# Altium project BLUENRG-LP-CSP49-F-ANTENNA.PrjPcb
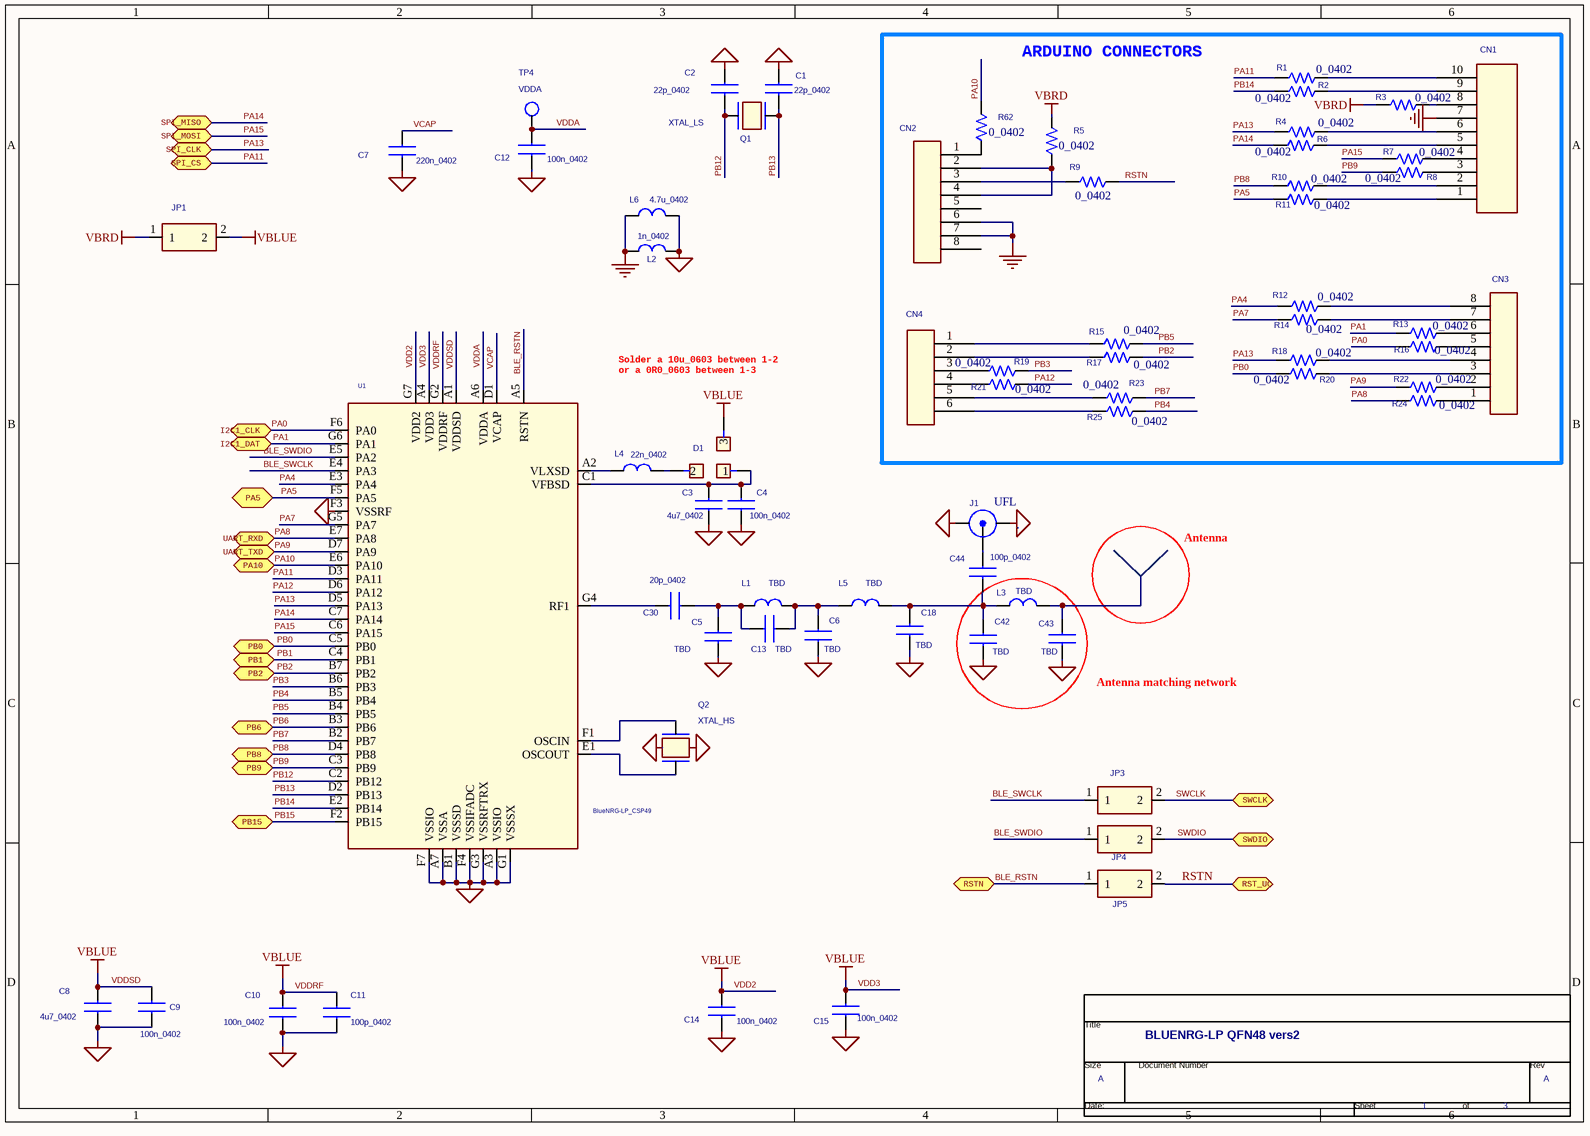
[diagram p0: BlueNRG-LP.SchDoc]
3 sheets, 160 parts. Net scope: flat (ports and power ports of the same name join across sheets).
Board file: BLUENRG-LP_CSP49_F_ANTENNA.PcbDoc
Sheets:
  BlueNRG-LP.SchDoc
  Supply.SchDoc
  USB_MICRO.SchDoc

## Sheet BlueNRG-LP.SchDoc
size 297 x 209 mm

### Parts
(Parts that share a designator on the sheet are numbered #1, #2 ... from top to bottom, then left to right.)
*#1  Page Count: 3  Page Number: 1  Page Size: A  Title: BLUENRG-LP QFN48 vers2  (hidden comment: TitleBlock0)  (graphical)
C1  22p_0402  [0402_CAP_NP]
C2  22p_0402  [0402_CAP_NP]
C3  4u7_0402  [0402_CAP_NP]
C4  100n_0402  [0402_CAP_NP]
C5  TBD  [0402_CAP_NP]
C6  TBD  [0402_CAP_NP]
C7  220n_0402  [0402_CAP_NP]
C8  4u7_0402  [0402_CAP_NP]
C9  100n_0402  [0402_CAP_NP]
C10  100n_0402  [0402_CAP_NP]
C11  100p_0402  [0402_CAP_NP]
C12  100n_0402  [0402_CAP_NP]
C13  TBD  [0402_CAP_NP]
C14  100n_0402  [0402_CAP_NP]
C15  100n_0402  [0402_CAP_NP]
C18  TBD  [0402_CAP_NP]
C30  20p_0402  [0402_CAP_NP]
C42  TBD  [0402_CAP_NP]
C43  TBD  [0402_CAP_NP]
C44  100p_0402  [0402_CAP_NP]
CN1  CON10  [HDR1X10]  (value not drawn)
CN2  CON8  [HDR1X8]  (value not drawn)
CN3  CON8  [HDR1X8]  (value not drawn)
CN4  CON6  [HDR1X6]  (value not drawn)
D1  DEV3L  [DEV3L0603_VERS1]  (value not drawn)
J1  UFL  [UFL_SMT]
JP1  JUMPER 2  [HDR 2 X 1 M]  (value not drawn)
JP3  JUMPER 2  [HDR 2 X 1 M]  (value not drawn)
JP4  JUMPER 2  [HDR 2 X 1 M]  (value not drawn)
JP5  JUMPER 2  [HDR 2 X 1 M]  (value not drawn)
L1  TBD  [0402-A]
L2  1n_0402  [0402-A]
L3  TBD  [0402-A]
L4  22n_0402  [0402-A]
L5  TBD  [0402-A]
L6  4.7u_0402  [CAP 0603]
Q1  XTAL_LS  [NX2012SA]
Q2  XTAL_HS  [NX2016SA]
R1  0_0402  [0402_RESISTOR]
R2  0_0402  [0402_RESISTOR]
R3  0_0402  [0402_RESISTOR]
R4  0_0402  [0402_RESISTOR]
R5  0_0402  [0402_RESISTOR]
R6  0_0402  [0402_RESISTOR]
R7  0_0402  [0402_RESISTOR]
R8  0_0402  [0402_RESISTOR]
R9  0_0402  [0402_RESISTOR]
R10  0_0402  [0402_RESISTOR]
R11  0_0402  [0402_RESISTOR]
R12  0_0402  [0402_RESISTOR]
R13  0_0402  [0402_RESISTOR]
R14  0_0402  [0402_RESISTOR]
R15  0_0402  [0402_RESISTOR]
R16  0_0402  [0402_RESISTOR]
R17  0_0402  [0402_RESISTOR]
R18  0_0402  [0402_RESISTOR]
R19  0_0402  [0402_RESISTOR]
R20  0_0402  [0402_RESISTOR]
R21  0_0402  [0402_RESISTOR]
R22  0_0402  [0402_RESISTOR]
R23  0_0402  [0402_RESISTOR]
R24  0_0402  [0402_RESISTOR]
R25  0_0402  [0402_RESISTOR]
R62  0_0402  [0402_RESISTOR]
TP4  VDDA  [FIDUCIAL]
U1  BlueNRG-LP_CSP49  [WLCSP49_REV1]

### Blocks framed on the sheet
ARDUINO CONNECTORS: CN1-CN4 R1-R25 R62

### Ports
I2C1_CLK (bidir), I2C1_DAT (bidir), PA5 (bidir), PA10 (bidir), PB0 (bidir), PB1 (bidir), PB2 (bidir), PB6 (bidir), PB8 (bidir), PB9 (bidir), PB15 (bidir), RST_UC (bidir), RSTN (bidir), SPI_CLK (bidir), SPI_CS (bidir), SPI_MISO (bidir), SPI_MOSI (bidir), SWCLK (bidir), SWDIO (bidir), UART_RXD (bidir), UART_TXD (bidir)

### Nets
GND: CN1.7 CN2.6 CN2.7 L2.1 L6.1
GND_RF: C1.1 C2.1 C3.1 C4.1 C5.1 C6.1 C7.1 C8.1 C9.1 C10.1 C11.1 C12.1 C14.1 C15.1 C18.1 C42.1 C43.1 J1.1 J1.3 L2.2 L6.2 Q2.2 Q2.4(gnd1) U1.A3(VSSIO) U1.A7(VSSA) U1.B1(VSSSD) U1.F3(VSSRF) U1.F4(VSSIFADC) U1.F7(VSSIO) U1.G1(VSSSX) U1.G3(VSSRFTRX)
VBRD: JP1.1 R3.1 R5.2  [project net VDD_1]
VDD2: C8.2 C9.2 C10.2 C11.2 C14.2 C15.2 D1.3 JP1.2 U1.A1(VDDSD) U1.A4(VDD3) U1.G2(VDDRF) U1.G7(VDD2)  [also labelled VBLUE, VDD3, VDDRF, VDDSD]
BLE_RSTN: JP5.1 U1.A5(RSTN) ; port RSTN
BLE_SWCLK: JP3.1 U1.E4(PA3)
BLE_SWDIO: JP4.1 U1.E5(PA2)
PA0: R16.1 U1.F6(PA0) ; port I2C1_CLK
PA1: R13.1 U1.G6(PA1) ; port I2C1_DAT
PA4: R12.1 U1.E3(PA4)
PA5: R11.1 U1.F5(PA5) ; port PA5
PA7: R14.1 U1.G5(PA7)
PA8: R24.1 U1.E7(PA8) ; port UART_RXD
PA9: R22.1 U1.D7(PA9) ; port UART_TXD
PA10: R62.2 U1.E6(PA10) ; port PA10
PA11: R1.1 U1.D3(PA11) ; port SPI_CS
PA12: R21.2 U1.D6(PA12)
PA13: R4.1 R18.1 U1.D5(PA13) ; port SPI_CLK
PA14: R6.1 U1.C7(PA14) ; port SPI_MISO
PA15: R7.1 U1.C6(PA15) ; port SPI_MOSI
PB0: R20.1 U1.C5(PB0) ; port PB0
PB1: U1.C4(PB1) ; port PB1
PB2: R17.2 U1.B7(PB2) ; port PB2
PB3: R19.2 U1.B6(PB3)
PB4: R25.2 U1.B5(PB4)
PB5: R15.2 U1.B4(PB5)
PB6: U1.B3(PB6) ; port PB6
PB7: R23.2 U1.B2(PB7)
PB8: R10.1 U1.D4(PB8) ; port PB8
PB9: R8.1 U1.C3(PB9) ; port PB9
PB12: C2.2 Q1.1 U1.C2(PB12)
PB13: C1.2 Q1.2 U1.D2(PB13)
PB14: R2.1 U1.E2(PB14)
PB15: U1.F2(PB15) ; port PB15
RSTN: JP5.2 R9.2 ; port RST_UC
SWCLK: JP3.2 ; port SWCLK
SWDIO: JP4.2 ; port SWDIO
VCAP: C7.2 U1.D1(VCAP)
VDDA: C12.2 TP4.1(TP) U1.A6(VDDA)
NetC3_2: C3.2 C4.2 D1.1 U1.C1(VFBSD)
NetC5_2: C5.2 C13.2 C30.1 L1.1
NetC6_2: C6.2 C13.1 L1.2 L5.1
NetC18_2: C18.2 C42.2 C44.1 L3.1 L5.2
NetC30_2: C30.2 U1.G4(RF1)
NetC43_2: C43.2 L3.2
NetC44_2: C44.2 J1.2
NetCN1_1: CN1.1 R11.2
NetCN1_2: CN1.2 R10.2
NetCN1_3: CN1.3 R8.2
NetCN1_4: CN1.4 R7.2
NetCN1_5: CN1.5 R6.2
NetCN1_6: CN1.6 R4.2
NetCN1_8: CN1.8 R3.2
NetCN1_9: CN1.9 R2.2
NetCN1_10: CN1.10 R1.2
NetCN2_1: CN2.1 R62.1
NetCN2_2: CN2.2 CN2.4 R5.1
NetCN2_3: CN2.3 R9.1
NetCN3_1: CN3.1 R24.2
NetCN3_2: CN3.2 R22.2
NetCN3_3: CN3.3 R20.2
NetCN3_4: CN3.4 R18.2
NetCN3_5: CN3.5 R16.2
NetCN3_6: CN3.6 R13.2
NetCN3_7: CN3.7 R14.2
NetCN3_8: CN3.8 R12.2
NetCN4_1: CN4.1 R15.1
NetCN4_2: CN4.2 R17.1
NetCN4_3: CN4.3 R19.1
NetCN4_4: CN4.4 R21.1
NetCN4_5: CN4.5 R23.1
NetCN4_6: CN4.6 R25.1
NetD1_2: D1.2 L4.2
NetL4_1: L4.1 U1.A2(VLXSD)
NetQ2_1: Q2.1 U1.F1(OSCIN)
NetQ2_3: Q2.3 U1.E1(OSCOUT)

Not connected (* = marked no-connect by the designer): CN2 5 8

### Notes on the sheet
- Solder a 10u_0603 between 1-2
  or a 0R0_0603 between 1-3
- Antenna
- (near C43) Antenna matching network

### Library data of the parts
*#1 = TitleBlock0: Doc: BLUENRG-248 APPLICATION BOARD
C1 C6 C10 C12 = MURATA GRM36: COMPSIDE: TOP; COMPLOC: [-1955.000,605.000]; COMPROT: 180; COMPGROUP: 0; COMPFIXED: NO; COMPHEIGHT: 0.000
C2-C5 C7-C9 C11 C13-C15 C18 C30 C42-C44 = MURATA GRM36: COMPHEIGHT: 0.000; MEMORY: NO; COMPGROUP: 0; COMPROT: 180; COMPLOC: [-1955.000,605.000]; COMPSIDE: TOP
D1 = DEV3L_0
J1 = UFL: 50 Ohms, SMA Jack Receptacle, Edge Mount, .25µm Gold (Au) Plating; Manufacturer: Molex; Manufacturer’s ordering code / Orderable Part Number: 73251-1150; STEVAL: FKIxxx; Value: SMA_RF
JP1 JP3-JP5 = Buzzer
L1-L6 = IND_short
Q1 = QUARZO
Q2 = NX3225SA: COMPSIDE: TOP; COMPLOC: [-2158.000,974.000]; COMPROT: 180; COMPGROUP: 0; COMPFIXED: NO; COMPHEIGHT: 0.000
R1-R25 R62 = R_Dup1: PSpiceTemplate: R^@REFDES %1 %2 ?TOLERANCE¦R^@REFDES¦ @VALUE  ?TOLERANCE¦\n.model R^@REFDES RES R=1 DEV=@TOLERANCE%¦
TP4 = T POINT R: COMPHEIGHT: 10.000; MEMORY: NO; COMPGROUP: 0; COMPROT: 270; COMPLOC: [734.867,493.467]; COMPSIDE: TOP
U1 = BlueNRG-LP_CSP49_2

## Sheet Supply.SchDoc
size 297 x 209 mm
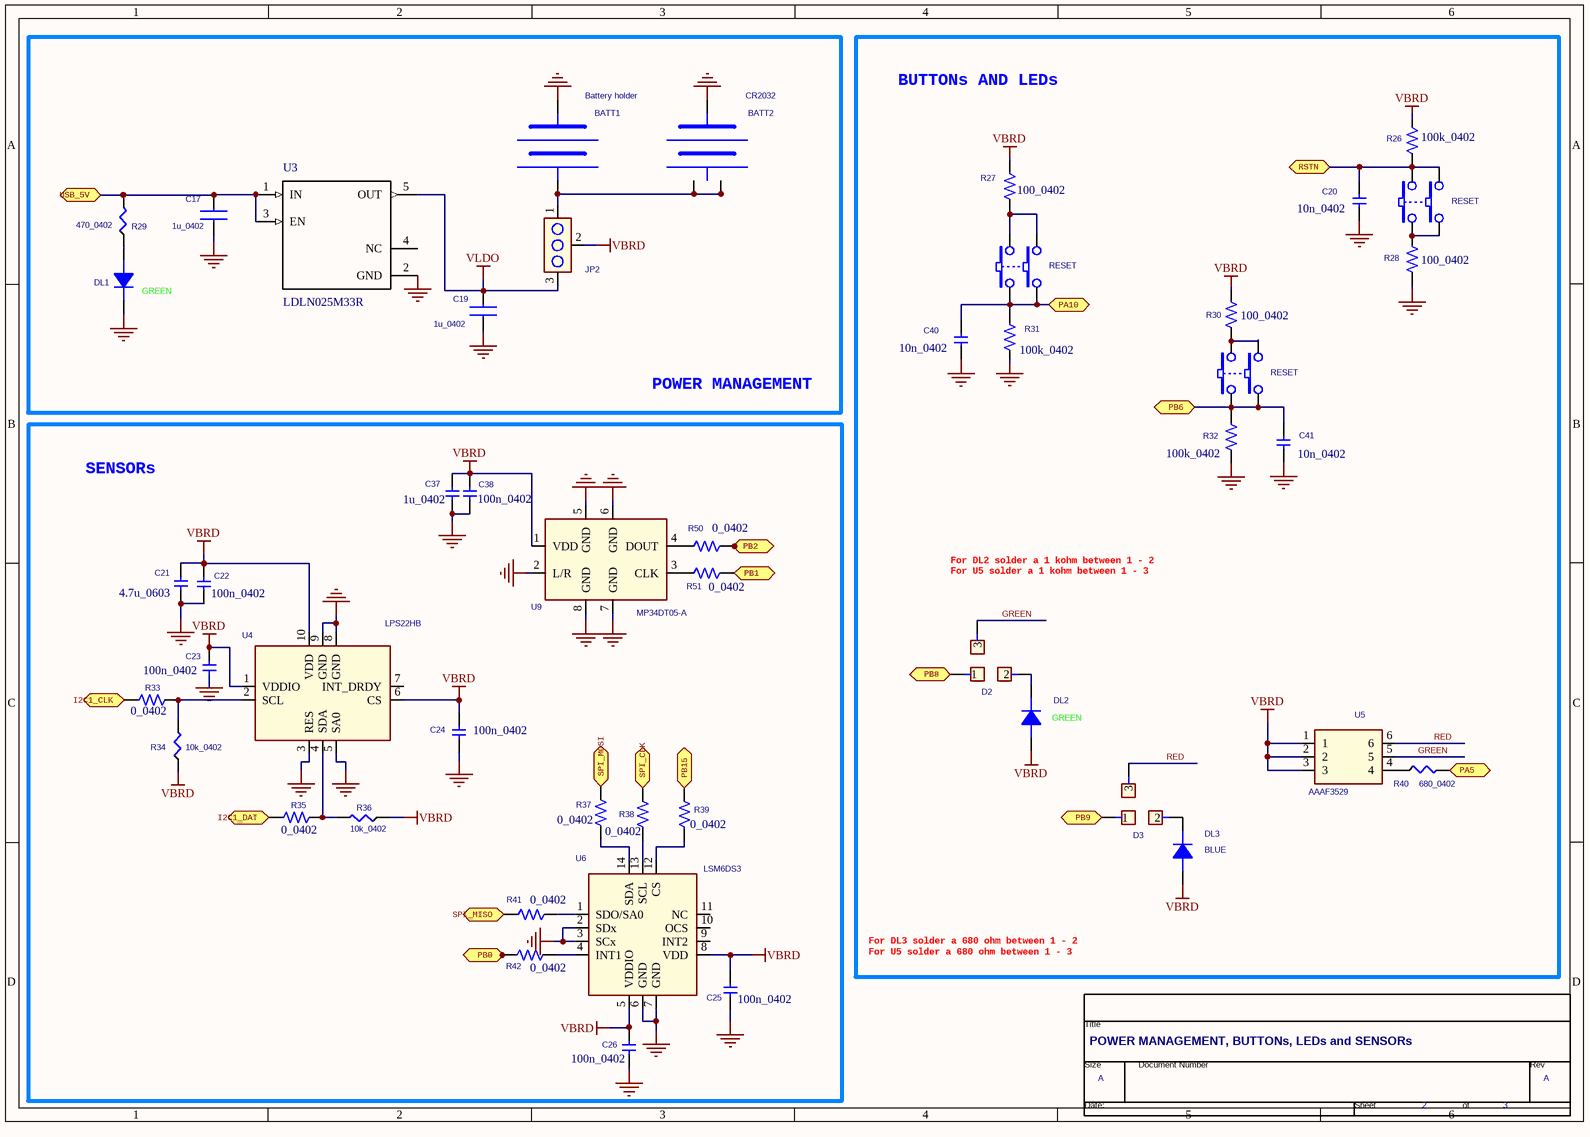
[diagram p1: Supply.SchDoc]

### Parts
(Parts that share a designator on the sheet are numbered #1, #2 ... from top to bottom, then left to right.)
*#2  Page Count: 3  Page Number: 2  Page Size: A  Title: POWER MANAGEMENT, BUTTONs, LEDs and SENSORs  (hidden comment: TitleBlock0)  (graphical)
BATT1  Battery holder  [PACCO_BATT_2]
BATT2  CR2032  [CR2032_BATTERY_HOLDER]
C17  1u_0402  [0402_CAP_NP]
C19  1u_0402  [0402_CAP_NP]
C20  10n_0402  [0402_CAP_NP]
C21  4.7u_0603  [0603_CAP_NP]
C22  100n_0402  [0402_CAP_NP]
C23  100n_0402  [0402_CAP_NP]
C24  100n_0402  [0402_CAP_NP]
C25  100n_0402  [0402_CAP_NP]
C26  100n_0402  [0402_CAP_NP]
C37  1u_0402  [0402_CAP_NP]
C38  100n_0402  [0402_CAP_NP]
C40  10n_0402  [0402_CAP_NP]
C41  10n_0402  [0402_CAP_NP]
D2  DEV3L  [DEV3L0603]  (value not drawn)
D3  DEV3L  [DEV3L0603]  (value not drawn)
DL1  Diodo_led  [SMD _LED]  (value not drawn)
DL2  Diodo_led  [SMD _LED]  (value not drawn)
DL3  BLUE  [SMD _LED]
JP2  Jumper 3  [HDR 3 X 1 M]  (value not drawn)
R26  100k_0402  [0402_RESISTOR]
R27  100_0402  [0402_RESISTOR]
R28  100_0402  [0402_RESISTOR]
R29  470_0402  [0402_RESISTOR]
R30  100_0402  [0402_RESISTOR]
R31  100k_0402  [0402_RESISTOR]
R32  100k_0402  [0402_RESISTOR]
R33  0_0402  [0402_RESISTOR]
R34  10k_0402  [0402_RESISTOR]
R35  0_0402  [0402_RESISTOR]
R36  10k_0402  [0402_RESISTOR]
R37  0_0402  [0402_RESISTOR]
R38  0_0402  [0402_RESISTOR]
R39  0_0402  [0402_RESISTOR]
R40  680_0402  [0402_RESISTOR]
R41  0_0402  [0402_RESISTOR]
R42  0_0402  [0402_RESISTOR]
R50  value 0_0402  [0402_RESISTOR]  (hidden comment: NC)
R51  value 0_0402  [0402_RESISTOR]  (hidden comment: NC)
SW1  RESET  [B3FS_SWITCH]
SW2  RESET  [B3FS_SWITCH]
SW3  RESET  [B3FS_SWITCH]
U3  LDLN025M33R  [*SOT95P280X145-5N]
U4  LPS22HB  [HLGA-10L-2X2]
U5  AAAF3529  [AAAF3529L]
U6  LSM6DS3  [LGA14]
U9  MP34DT05-A  [MP34DT05-A]

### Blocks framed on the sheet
POWER MANAGEMENT: BATT1 BATT2 C17 C19 DL1 JP2 R29 U3
BUTTONs AND LEDs: C20 C40 C41 D2 D3 DL2 DL3 R26-R28 R30-R32 R40 SW1-SW3 U5
SENSORs: C21-C26 C37 C38 R33-R39 R41 R42 R50 R51 U4 U6 U9

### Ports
I2C1_CLK (bidir), I2C1_DAT (bidir), PA5 (bidir), PA10 (bidir), PB0 (bidir), PB1 (bidir), PB2 (bidir), PB6 (bidir), PB8 (bidir), PB9 (bidir), PB15 (bidir), RSTN (bidir), SPI_CLK (bidir), SPI_MISO (bidir), SPI_MOSI (bidir), USB_5V (bidir)

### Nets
GND: BATT1.2(GND) BATT2.3(GND) C17.1 C19.1 C20.1 C21.1 C22.1 C23.1 C24.1 C25.1 C26.1 C37.1 C38.1 C40.1 C41.1 DL1.2(CATHODE) R28.2 R31.2 R32.2 U3.2(GND) U4.3(RES) U4.5(SA0) U4.8(GND) U4.9(GND) U6.2(SDx) U6.3(SCx) U6.6(GND) U6.7(GND) U9.2(L/R) U9.5(GND) U9.6(GND) U9.7(GND) U9.8(GND)
VBRD: C21.2 C22.2 C23.2 C24.2 C25.2 C26.2 C37.2 C38.2 DL2.1(ANODE) DL3.1(ANODE) JP2.2 R26.1 R27.1 R30.1 R34.1 R36.1 U4.1(VDDIO) U4.6(CS) U4.10(VDD) U5.1 U5.2 U5.3 U6.5(VDDIO) U6.8(VDD) U9.1(VDD)  [project net VDD_1]
VLDO: C19.2 JP2.3 U3.5(OUT)
BLE_RSTN: C20.2 R26.2 SW1.3 SW1.4 ; port RSTN
GREEN: D2.3 U5.5
PA0: R33.1 ; port I2C1_CLK
PA1: R35.1 ; port I2C1_DAT
PA5: R40.2 ; port PA5
PA10: C40.2 R31.1 SW2.1 SW2.2 ; port PA10
PA13: R38.2 ; port SPI_CLK
PA14: R41.1 ; port SPI_MISO
PA15: R37.2 ; port SPI_MOSI
PB0: R42.1 ; port PB0
PB1: R51.1 ; port PB1
PB2: R50.1 ; port PB2
PB6: C41.2 R32.1 SW3.1 SW3.2 ; port PB6
PB8: D2.1 ; port PB8
PB9: D3.1 ; port PB9
PB15: R39.2 ; port PB15
RED: D3.3 U5.6
NetBATT1_1: BATT1.1(VP) BATT2.1(VP) BATT2.2(VP) JP2.1
NetC17_2: C17.2 R29.2 U3.1(IN) U3.3(EN) ; port USB_5V
NetD2_2: D2.2 DL2.2(CATHODE)
NetD3_2: D3.2 DL3.2(CATHODE)
NetDL1_1: DL1.1(ANODE) R29.1
NetR27_2: R27.2 SW2.3 SW2.4
NetR28_1: R28.1 SW1.1 SW1.2
NetR30_2: R30.2 SW3.3 SW3.4
NetR33_2: R33.2 R34.2 U4.2(SCL)
NetR35_2: R35.2 R36.2 U4.4(SDA)
NetR37_1: R37.1 U6.14(SDA)
NetR38_1: R38.1 U6.13(SCL)
NetR39_1: R39.1 U6.12(CS)
NetR40_1: R40.1 U5.4
NetR41_2: R41.2 U6.1(SDO/SA0)
NetR42_2: R42.2 U6.4(INT1)
NetR50_2: R50.2 U9.4(DOUT)
NetR51_2: R51.2 U9.3(CLK)

Not connected (* = marked no-connect by the designer): U3 4(NC); U4 7(INT_DRDY); U6 9(INT2) 10(OCS) 11(NC)

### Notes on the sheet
- (near DL1) GREEN
- (near D2) For DL2 solder a 1 kohm between 1 - 2
  For U5 solder a 1 kohm between 1 - 3
- (near DL2) GREEN
- (near *#2) For DL3 solder a 680 ohm between 1 - 2
  For U5 solder a 680 ohm between 1 - 3

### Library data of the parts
*#2 = TitleBlock0: Doc: BLUENRG-2 APPLICATION BOARD
BATT2 = Battery holder_0
C17 = MURATA GRM36: as C2 on sheet BlueNRG-LP
C19 = MURATA GRM36: as C1 on sheet BlueNRG-LP
C20 C40 C41 = C: PSpiceTemplate: C^@REFDES %1 %2 ?TOLERANCE¦C^@REFDES¦ @VALUE ?IC/IC=@IC/ ?TOLERANCE¦\n.model C^@REFDES CAP C=1 DEV=@TOLERANCE%¦; COMPSIDE: TOP; COMPLOC: [-4703.000,-13410.000]; COMPROT: 270; COMPGROUP: 0; COMPFIXED: NO; COMPHEIGHT: 0.000
C21 C23 C25 C26 C38 = C: PSpiceTemplate: C^@REFDES %1 %2 ?TOLERANCE¦C^@REFDES¦ @VALUE ?IC/IC=@IC/ ?TOLERANCE¦\n.model C^@REFDES CAP C=1 DEV=@TOLERANCE%¦; COMPHEIGHT: 0.000; MEMORY: NO; COMPGROUP: 0; COMPROT: 270; COMPLOC: [-4302.000,-13410.000]; COMPSIDE: TOP
C22 C24 C37 = C: PSpiceTemplate: C^@REFDES %1 %2 ?TOLERANCE¦C^@REFDES¦ @VALUE ?IC/IC=@IC/ ?TOLERANCE¦\n.model C^@REFDES CAP C=1 DEV=@TOLERANCE%¦; COMPSIDE: TOP; COMPLOC: [-4302.000,-13410.000]; COMPROT: 270; COMPGROUP: 0; COMPFIXED: NO; COMPHEIGHT: 0.000
D2 D3 = DEV3L_0
DL1 = Diodo_led: COMPSIDE: TOP; COMPLOC: [607.800,3484.867]; COMPROT: 0; COMPFIXED: NO; COMPHEIGHT: 0.000
DL2 = Diodo_led: COMPHEIGHT: 0.000; MEMORY: NO; COMPGROUP: 0; COMPLOC: [607.800,3484.867]; COMPSIDE: TOP
DL3 = Diodo_led: FPLIST: SM/D1206_S; COMPSIDE: TOP; COMPLOC: [1254.733,908.600]; COMPROT: 270; COMPGROUP: 0; COMPFIXED: NO; COMPHEIGHT: 0.000
R26 = R_Dup1: PSpiceTemplate: R^@REFDES %1 %2 ?TOLERANCE¦R^@REFDES¦ @VALUE  ?TOLERANCE¦\n.model R^@REFDES RES R=1 DEV=@TOLERANCE%¦; COMPSIDE: TOP; COMPLOC: [-4614.000,-13410.000]; COMPROT: 270; COMPGROUP: 0; COMPFIXED: NO; COMPHEIGHT: 0.000
R27 = R_Dup1: PSpiceTemplate: R^@REFDES %1 %2 ?TOLERANCE¦R^@REFDES¦ @VALUE  ?TOLERANCE¦\n.model R^@REFDES RES R=1 DEV=@TOLERANCE%¦; COMPSIDE: TOP; COMPLOC: [-4218.000,-13410.000]; COMPROT: 270; COMPGROUP: 0; COMPFIXED: NO; COMPHEIGHT: 0.000
R28 = R_Dup1: PSpiceTemplate: R^@REFDES %1 %2 ?TOLERANCE¦R^@REFDES¦ @VALUE  ?TOLERANCE¦\n.model R^@REFDES RES R=1 DEV=@TOLERANCE%¦; COMPHEIGHT: 0.000; MEMORY: NO; COMPGROUP: 0; COMPROT: 90; COMPLOC: [-4786.000,-13465.000]; COMPSIDE: TOP
R29 = R: COMPSIDE: TOP; COMPLOC: [1164.933,2712.533]; COMPROT: 0; COMPFIXED: NO; COMPHEIGHT: 0.000
R30 = R_Dup1: PSpiceTemplate: R^@REFDES %1 %2 ?TOLERANCE¦R^@REFDES¦ @VALUE  ?TOLERANCE¦\n.model R^@REFDES RES R=1 DEV=@TOLERANCE%¦; COMPHEIGHT: 0.000; MEMORY: NO; COMPGROUP: 0; COMPROT: 270; COMPLOC: [-4614.000,-13410.000]; COMPSIDE: TOP
R31 = R_Dup1: PSpiceTemplate: R^@REFDES %1 %2 ?TOLERANCE¦R^@REFDES¦ @VALUE  ?TOLERANCE¦\n.model R^@REFDES RES R=1 DEV=@TOLERANCE%¦; COMPSIDE: TOP; COMPLOC: [-4389.000,-13465.000]; COMPROT: 90; COMPGROUP: 0; COMPFIXED: NO; COMPHEIGHT: 0.000
R32 = R_Dup1: PSpiceTemplate: R^@REFDES %1 %2 ?TOLERANCE¦R^@REFDES¦ @VALUE  ?TOLERANCE¦\n.model R^@REFDES RES R=1 DEV=@TOLERANCE%¦; COMPSIDE: TOP; COMPLOC: [-4786.000,-13465.000]; COMPROT: 90; COMPGROUP: 0; COMPFIXED: NO; COMPHEIGHT: 0.000
R33 R35 R37-R39 R41 R42 R50 R51 = R_Dup1: as R1 on sheet BlueNRG-LP
R34 R36 = R: FPLIST: SM/R_0805; COMPSIDE: TOP; COMPLOC: [1528.600,2164.067]; COMPROT: 180; COMPGROUP: 0; COMPFIXED: NO; COMPHEIGHT: 0.000
R40 = R: FPLIST: SM/R_0805; COMPSIDE: TOP; COMPLOC: [1529.600,1899.067]; COMPROT: 180; COMPGROUP: 0; COMPFIXED: NO; COMPHEIGHT: 0.000
SW1 = SWITCH-1: COMPHEIGHT: 8.000; MEMORY: NO; COMPGROUP: 0; COMPLOC: [-4725.000,-13849.000]; COMPSIDE: TOP; FPLIST: PULSE2_479-1508
SW2 SW3 = SWITCH-1: FPLIST: PULSE2_479-1508; COMPSIDE: TOP; COMPLOC: [-4725.000,-13849.000]; COMPROT: 0; COMPFIXED: NO; COMPHEIGHT: 8.000
U3 = LDLN025M33R: LDLN025 Series 3.3 V 250 mA Surface Mount Fixed Ultra Low Noise LDO - SOT-23-5L; MF: STMicroelectronics
U4 = LPS25HB
U9 = MP34DT05-A_0

## Sheet USB_MICRO.SchDoc
size 297 x 209 mm
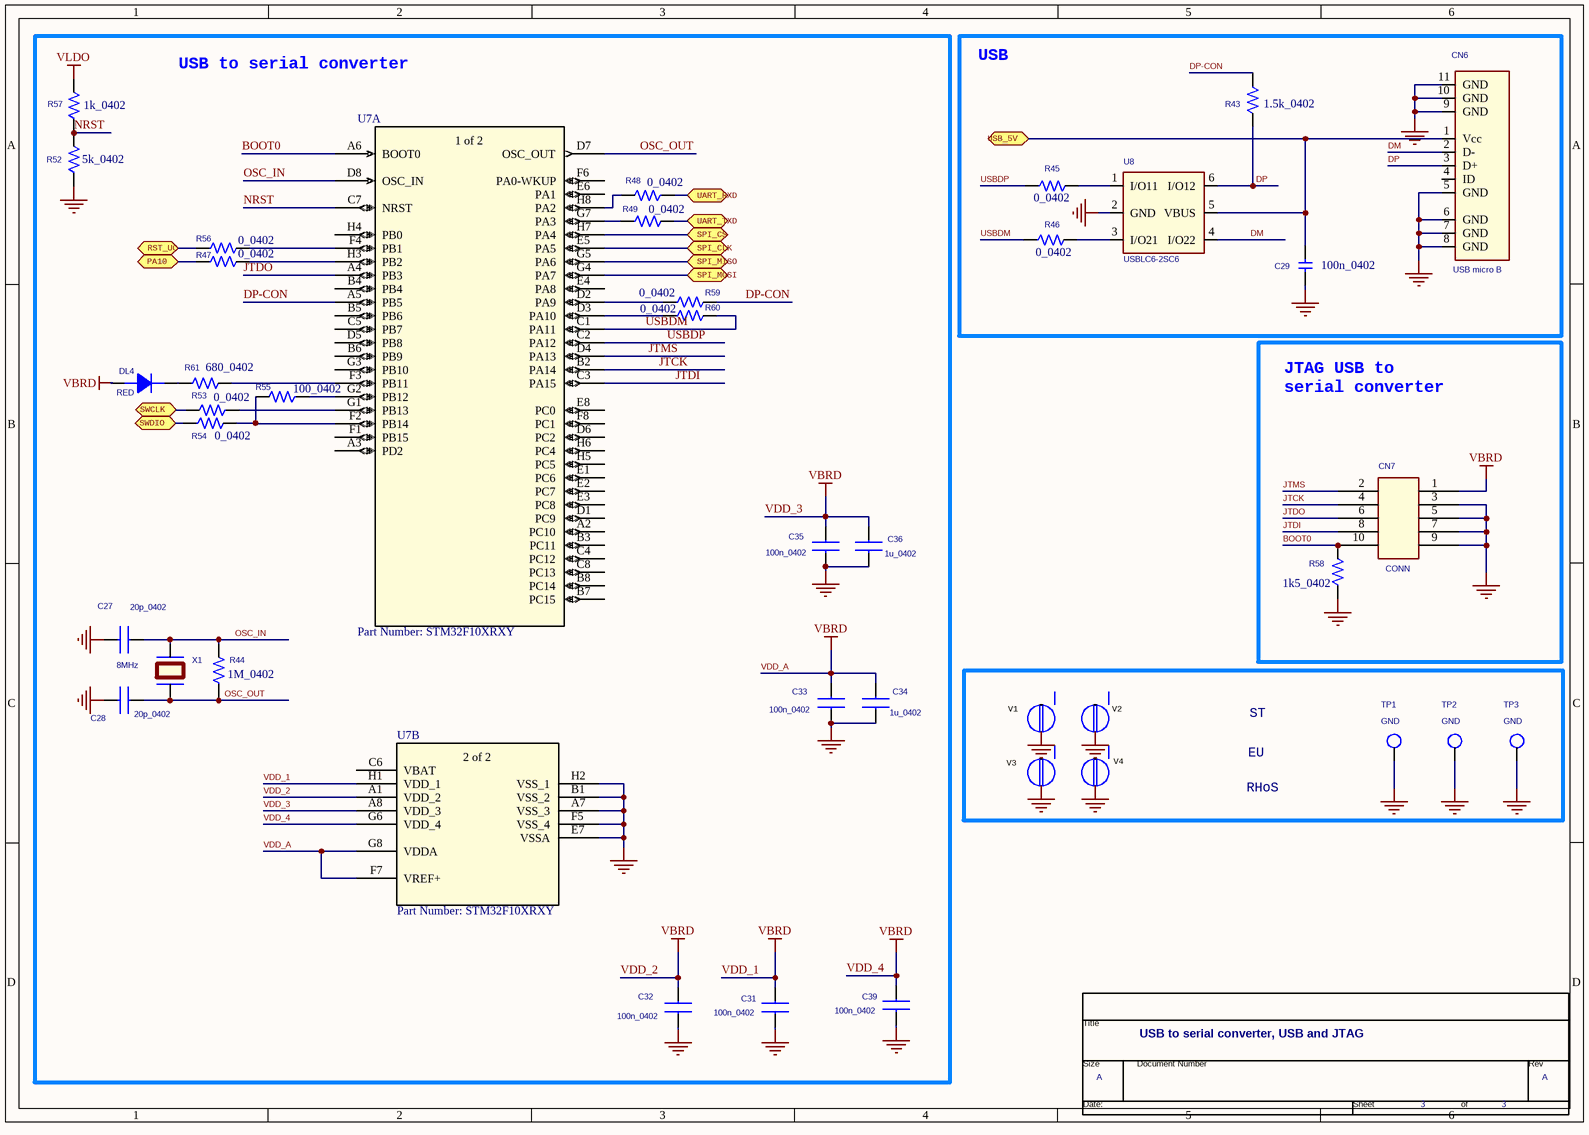
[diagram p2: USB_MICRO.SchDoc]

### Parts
(Parts that share a designator on the sheet are numbered #1, #2 ... from top to bottom, then left to right.)
*#3  Page Count: 3  Page Size: A  Title: USB to serial converter, USB and JTAG  (hidden comment: TitleBlock0)  (graphical)
C27  20p_0402  [0402_CAP_NP]
C28  20p_0402  [0402_CAP_NP]
C29  100n_0402  [0402_CAP_NP]
C31  100n_0402  [0402_CAP_NP]
C32  100n_0402  [0402_CAP_NP]
C33  100n_0402  [0402_CAP_NP]
C34  1u_0402  [0402_CAP_NP]
C35  100n_0402  [0402_CAP_NP]
C36  1u_0402  [0402_CAP_NP]
C39  100n_0402  [0402_CAP_NP]
CN6  USB micro B  [MICRO USB]
CN7  CONN  [AMPMODE10_50M]
DL4  RED  [SMD _LED]
R43  1.5k_0402  [0402_RESISTOR]
R44  1M_0402  [0402_RESISTOR]
R45  0_0402  [0402_RESISTOR]
R46  0_0402  [0402_RESISTOR]
R47  0_0402  [0402_RESISTOR]
R48  0_0402  [0402_RESISTOR]
R49  0_0402  [0402_RESISTOR]
R52  5k_0402  [0402_RESISTOR]
R53  0_0402  [0402_RESISTOR]
R54  0_0402  [0402_RESISTOR]
R55  100_0402  [0402_RESISTOR]
R56  0_0402  [0402_RESISTOR]
R57  1k_0402  [0402_RESISTOR]
R58  1k5_0402  [0402_RESISTOR]
R59  0_0402  [0402_RESISTOR]
R60  0_0402  [0402_RESISTOR]
R61  680_0402  [0402_RESISTOR]
ST1  stlogo  [stlogo]  (value not drawn)
ST2  EUlogo  [EU_ROHS_1_2]  (value not drawn)
ST3  RHoSlogo  [CH_ROHS_2]  (value not drawn)
TP1  GND  [TESTP]
TP2  GND  [TESTP]
TP3  GND  [TESTP]
U7  Part Number: STM32F10XRXY  [PCBComponent_1]  (parts A,B of 2)
U8  USBLC6-2SC6  [SOT23-6L_S]
V1  VITE  [FORO 3MM]  (value not drawn)
V2  VITE  [FORO 3MM]  (value not drawn)
V3  VITE  [FORO 3MM]  (value not drawn)
V4  VITE  [FORO 3MM]  (value not drawn)
X1  8MHz  [QUARZO]

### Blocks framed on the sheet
USB to serial converter: C27 C28 C31-C36 C39 DL4 R44 R47-R49 R52-R57 R59-R61 U7 X1
USB: C29 CN6 R43 R45 R46 U8

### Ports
PA10 (bidir), RST_UC (bidir), SPI_CLK (bidir), SPI_CS (bidir), SPI_MISO (bidir), SPI_MOSI (bidir), SWCLK (bidir), SWDIO (bidir), UART_RXD (bidir), UART_TXD (bidir), USB_5V (bidir)

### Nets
GND: C27.2 C28.2 C29.2 C31.1 C32.1 C33.1 C34.1 C35.1 C36.1 C39.1 CN6.5(GND) CN6.6(GND) CN6.7(GND) CN6.8(GND) CN6.9(GND) CN6.10(GND) CN6.11(GND) CN7.3(+) CN7.5(+) CN7.7(+) CN7.9(+) R52.1 R58.1 TP1.1(TP) TP2.1(TP) TP3.1(TP) U7.A7(VSS_3) U7.B1(VSS_2) U7.E7(VSSA) U7.F5(VSS_4) U7.H2(VSS_1) U8.2(GND) V1.1 V2.1 V3.1 V4.1
VDD_1: C31.2 C32.2 C33.2 C34.2 C35.2 C36.2 C39.2 CN7.1(+) DL4.1(ANODE) U7.A1(VDD_2) U7.A8(VDD_3) U7.F7(VREF+) U7.G6(VDD_4) U7.G8(VDDA) U7.H1(VDD_1)  [also labelled VBRD, VDD_2, VDD_3, VDD_4, VDD_A]
VLDO: R57.2
BOOT0: CN7.10(+) R58.2 U7.A6(BOOT0)
DM: CN6.2(D-) U8.4(I/O22)
DP: CN6.3(D+) R43.2 U8.6(I/O12)
DP-CON: R43.1 R59.2 U7.A5(PB5)
JTCK: CN7.4(+) U7.B2(PA14)
JTDI: CN7.8(+) U7.C3(PA15)
JTDO: CN7.6(+) U7.A4(PB3)
JTMS: CN7.2(+) U7.D4(PA13)
NRST: R52.2 R57.1 U7.C7(NRST)
OSC_IN: C27.1 R44.2 U7.D8(OSC_IN) X1.2
OSC_OUT: C28.1 R44.1 U7.D7(OSC_OUT) X1.1
PA8: R48.1 ; port UART_RXD
PA9: R49.2 ; port UART_TXD
PA10: R47.1 ; port PA10
PA11: U7.H7(PA4) ; port SPI_CS
PA13: U7.E5(PA5) ; port SPI_CLK
PA14: U7.G5(PA6) ; port SPI_MISO
PA15: U7.G4(PA7) ; port SPI_MOSI
RSTN: R56.1 ; port RST_UC
SWCLK: R53.2 ; port SWCLK
SWDIO: R54.1 ; port SWDIO
USBDM: R46.1 R60.2 U7.C1(PA11)
USBDP: R45.1 U7.C2(PA12)
NetC17_2: C29.1 CN6.1(Vcc) U8.5(VBUS) ; port USB_5V
NetDL4_2: DL4.2(CATHODE) R61.1
NetR45_2: R45.2 U8.1(I/O11)
NetR46_2: R46.2 U8.3(I/O21)
NetR47_2: R47.2 U7.H3(PB2)
NetR48_2: R48.2 U7.H8(PA2)
NetR49_1: R49.1 U7.G7(PA3)
NetR53_1: R53.1 U7.G1(PB13)
NetR54_2: R54.2 R55.2 U7.F2(PB14)
NetR55_1: R55.1 U7.G2(PB12)
NetR56_2: R56.2 U7.F4(PB1)
NetR59_1: R59.1 U7.D2(PA9)
NetR60_1: R60.1 U7.D3(PA10)
NetR61_2: R61.2 U7.F3(PB11)

Not connected (* = marked no-connect by the designer): CN6 4(ID); U7 A2(PC10) A3(PD2) B3(PC11) B4(PB4) B5(PB6) B6(PB9) B7(PC15) B8(PC14) C4(PC12) C5(PB7) C6(VBAT) C8(PC13) D1(PC9) D5(PB8) D6(PC2) E1(PC6) E2(PC7) E3(PC8) E4(PA8) E6(PA1) E8(PC0) F1(PB15) F6(PA0-WKUP) F8(PC1) G3(PB10) H4(PB0) H5(PC5) H6(PC4)

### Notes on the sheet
- JTAG USB to
  serial converter
- (near V1) V1
- (near V2) V2
- V3
- V4

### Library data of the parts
*#3 = TitleBlock0: Doc: BLUENRG-2 APPLICATION BOARD
C27 C28 C31 C34 C36 C39 = MURATA GRM36: as C2 on sheet BlueNRG-LP
C29 = C: PSpiceTemplate: C^@REFDES %1 %2 ?TOLERANCE¦C^@REFDES¦ @VALUE ?IC/IC=@IC/ ?TOLERANCE¦\n.model C^@REFDES CAP C=1 DEV=@TOLERANCE%¦; COMPHEIGHT: 0.000; MEMORY: NO; COMPGROUP: 0; COMPROT: 270; COMPLOC: [814.800,3196.200]; COMPSIDE: TOP
C32 C33 C35 = MURATA GRM36: as C1 on sheet BlueNRG-LP
CN6 = USB micro B_0
CN7 = CON10AP
DL4 = Diodo_led: as DL3 on sheet Supply
R43 = R_Dup1: PSpiceTemplate: R^@REFDES %1 %2 ?TOLERANCE¦R^@REFDES¦ @VALUE  ?TOLERANCE¦\n.model R^@REFDES RES R=1 DEV=@TOLERANCE%¦; COMPHEIGHT: 0.000; MEMORY: NO; COMPGROUP: 0; COMPROT: 180; COMPLOC: [1050.667,2713.533]; COMPSIDE: TOP
R44 R45 = R_Dup1: PSpiceTemplate: R^@REFDES %1 %2 ?TOLERANCE¦R^@REFDES¦ @VALUE  ?TOLERANCE¦\n.model R^@REFDES RES R=1 DEV=@TOLERANCE%¦; COMPHEIGHT: 0.000; MEMORY: NO; COMPGROUP: 0; COMPROT: 180; COMPLOC: [1051.533,2790.267]; COMPSIDE: TOP
R46 R52 R57 R58 R60 R61 = R_Dup1: PSpiceTemplate: R^@REFDES %1 %2 ?TOLERANCE¦R^@REFDES¦ @VALUE  ?TOLERANCE¦\n.model R^@REFDES RES R=1 DEV=@TOLERANCE%¦; COMPHEIGHT: 0.000; MEMORY: NO; COMPGROUP: 0; COMPROT: 180; COMPLOC: [1219.333,2792.667]; COMPSIDE: TOP
R47-R49 R56 = R_Dup1: as R1 on sheet BlueNRG-LP
R53-R55 R59 = R_Dup1: PSpiceTemplate: R^@REFDES %1 %2 ?TOLERANCE¦R^@REFDES¦ @VALUE  ?TOLERANCE¦\n.model R^@REFDES RES R=1 DEV=@TOLERANCE%¦; COMPSIDE: TOP; COMPLOC: [1219.333,2792.667]; COMPROT: 180; COMPGROUP: 0; COMPFIXED: NO; COMPHEIGHT: 0.000
TP1 = T POINT R: COMPHEIGHT: 10.000; MEMORY: NO; COMPGROUP: 0; COMPROT: 270; COMPLOC: [1368.800,3252.867]; COMPSIDE: TOP
TP2 = T POINT R: COMPHEIGHT: 10.000; MEMORY: NO; COMPGROUP: 0; COMPROT: 270; COMPLOC: [3983.400,3545.533]; COMPSIDE: TOP
TP3 = T POINT R: COMPSIDE: TOP; COMPLOC: [734.867,493.467]; COMPROT: 270; COMPGROUP: 0; COMPFIXED: NO; COMPHEIGHT: 10.000
U7 = STM32F10XRXY: No Description Available; Vendor: STMicroelectronics
U8 = USBUFxxW6_0: COMPSIDE: TOP; COMPLOC: [940.933,3064.267]; COMPROT: 90; COMPGROUP: 0; COMPFIXED: NO; COMPHEIGHT: 0.000
V1 = VITE: COMPSIDE: TOP; COMPLOC: [3951.133,401.533]; COMPROT: 0; COMPFIXED: NO; COMPHEIGHT: 0.000
V2 = VITE: COMPSIDE: TOP; COMPLOC: [460.000,401.533]; COMPROT: 0; COMPFIXED: NO; COMPHEIGHT: 0.000
V3 = VITE: COMPSIDE: TOP; COMPLOC: [3942.867,4490.733]; COMPROT: 0; COMPFIXED: NO; COMPHEIGHT: 0.000
V4 = VITE: COMPSIDE: TOP; COMPLOC: [460.000,4504.667]; COMPROT: 0; COMPFIXED: NO; COMPHEIGHT: 0.000
X1 = QUARZO_Dup1: COMPSIDE: TOP; COMPLOC: [-4326.000,-12933.000]; COMPROT: 0; COMPFIXED: NO; COMPHEIGHT: 0.000

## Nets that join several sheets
GND: BlueNRG-LP (5 pins), Supply (33 pins), USB_MICRO (36 pins)
VDD_1: BlueNRG-LP (JP1.1 R3.1 R5.2), Supply (25 pins), USB_MICRO (15 pins)
VLDO: Supply (C19.2 JP2.3 U3.5), USB_MICRO (R57.2)
BLE_RSTN: BlueNRG-LP (JP5.1 U1.A5), Supply (C20.2 R26.2 SW1.3 SW1.4)
NetC17_2: Supply (C17.2 R29.2 U3.1 U3.3), USB_MICRO (C29.1 CN6.1 U8.5)
PA0: BlueNRG-LP (R16.1 U1.F6), Supply (R33.1)
PA1: BlueNRG-LP (R13.1 U1.G6), Supply (R35.1)
PA5: BlueNRG-LP (R11.1 U1.F5), Supply (R40.2)
PA8: BlueNRG-LP (R24.1 U1.E7), USB_MICRO (R48.1)
PA9: BlueNRG-LP (R22.1 U1.D7), USB_MICRO (R49.2)
PA10: BlueNRG-LP (R62.2 U1.E6), Supply (C40.2 R31.1 SW2.1 SW2.2), USB_MICRO (R47.1)
PA11: BlueNRG-LP (R1.1 U1.D3), USB_MICRO (U7.H7)
PA13: BlueNRG-LP (R4.1 R18.1 U1.D5), Supply (R38.2), USB_MICRO (U7.E5)
PA14: BlueNRG-LP (R6.1 U1.C7), Supply (R41.1), USB_MICRO (U7.G5)
PA15: BlueNRG-LP (R7.1 U1.C6), Supply (R37.2), USB_MICRO (U7.G4)
PB0: BlueNRG-LP (R20.1 U1.C5), Supply (R42.1)
PB1: BlueNRG-LP (U1.C4), Supply (R51.1)
PB2: BlueNRG-LP (R17.2 U1.B7), Supply (R50.1)
PB6: BlueNRG-LP (U1.B3), Supply (C41.2 R32.1 SW3.1 SW3.2)
PB8: BlueNRG-LP (R10.1 U1.D4), Supply (D2.1)
PB9: BlueNRG-LP (R8.1 U1.C3), Supply (D3.1)
PB15: BlueNRG-LP (U1.F2), Supply (R39.2)
RSTN: BlueNRG-LP (JP5.2 R9.2), USB_MICRO (R56.1)
SWCLK: BlueNRG-LP (JP3.2), USB_MICRO (R53.2)
SWDIO: BlueNRG-LP (JP4.2), USB_MICRO (R54.1)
